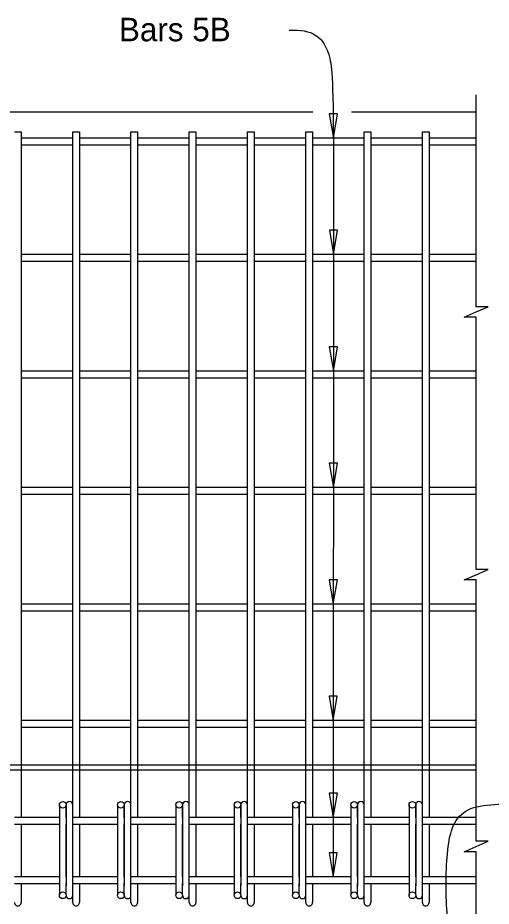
# Model space of a CAD drawing. Extents: x 120577.8 to 120649.9, y 120677.2 to 120721.6.
# Drawn here: x 120588.7 to 120592.76, y 120707.21 to 120714.84 of the extents above; entities that cross this region are included whole.
import ezdxf

# ---------------------------------------------------------------- set-up
doc = ezdxf.new("R2010")
doc.units = 0
for name, color, linetype in [('AdhocPoint_dp', 7, 'Continuous'), ('Patterning', 7, 'Continuous'), ('PlotBorder_dp', 7, 'Continuous'), ('TextMisc', 7, 'Continuous')]:
    doc.layers.add(name, color=color, linetype=linetype)

msp = doc.modelspace()

# ---------------------------------------------------------------- linework, layer by layer
at = {"layer": 'Patterning'}
for p, q in [((120588.669, 120713.8614), (120588.7263, 120713.8614)), ((120588.7263, 120713.8614), (120588.7263, 120707.9744)), ((120589.169, 120707.2437), (120589.169, 120713.8614)), ((120589.169, 120713.8614), (120589.2263, 120713.8614)), ((120589.2263, 120713.8614), (120589.2263, 120707.9744)), ((120589.669, 120707.2437), (120589.669, 120713.8614)), ((120589.669, 120713.8614), (120589.7263, 120713.8614)), ((120589.7263, 120713.8614), (120589.7263, 120707.9744)), ((120590.169, 120707.2437), (120590.169, 120713.8614)), ((120590.169, 120713.8614), (120590.2263, 120713.8614)), ((120590.2263, 120713.8614), (120590.2263, 120707.9744)), ((120590.669, 120707.2437), (120590.669, 120713.8614)), ((120590.669, 120713.8614), (120590.7263, 120713.8614)), ((120590.7263, 120713.8614), (120590.7263, 120707.9744)), ((120591.169, 120707.2437), (120591.169, 120713.8614)), ((120591.169, 120713.8614), (120591.2263, 120713.8614)), ((120591.2263, 120713.8614), (120591.2263, 120707.9744)), ((120591.669, 120707.2437), (120591.669, 120713.8614)), ((120591.669, 120713.8614), (120591.7263, 120713.8614)), ((120591.7263, 120713.8614), (120591.7263, 120707.9744)), ((120592.169, 120707.2437), (120592.169, 120713.8614)), ((120592.169, 120713.8614), (120592.2263, 120713.8614)), ((120592.2263, 120713.8614), (120592.2263, 120707.9744)), ((120589.0544, 120708.0827), (120589.0544, 120707.3067)), ((120589.1117, 120707.9744), (120589.1117, 120708.0827)), ((120589.1117, 120708.0827), (120589.1117, 120707.3872)), ((120589.5544, 120708.0827), (120589.5544, 120707.3067)), ((120589.6117, 120707.9744), (120589.6117, 120708.0827)), ((120589.6117, 120708.0827), (120589.6117, 120707.3872)), ((120590.0544, 120708.0827), (120590.0544, 120707.3067)), ((120590.1117, 120707.9744), (120590.1117, 120708.0827)), ((120590.1117, 120708.0827), (120590.1117, 120707.3872)), ((120590.5544, 120708.0827), (120590.5544, 120707.3067)), ((120590.6117, 120707.9744), (120590.6117, 120708.0827)), ((120590.6117, 120708.0827), (120590.6117, 120707.3872)), ((120591.0544, 120708.0827), (120591.0544, 120707.3067)), ((120591.1117, 120707.9744), (120591.1117, 120708.0827)), ((120591.1117, 120708.0827), (120591.1117, 120707.3872)), ((120591.5544, 120708.0827), (120591.5544, 120707.3067)), ((120591.6117, 120707.9744), (120591.6117, 120708.0827)), ((120591.6117, 120708.0827), (120591.6117, 120707.3872)), ((120592.0544, 120708.0827), (120592.0544, 120707.3067)), ((120592.1117, 120707.9744), (120592.1117, 120708.0827)), ((120592.1117, 120708.0827), (120592.1117, 120707.3872)), ((120588.7263, 120707.9172), (120588.7263, 120707.4641)), ((120589.1117, 120707.4641), (120589.1117, 120707.9172)), ((120589.2263, 120707.9172), (120589.2263, 120707.4641)), ((120589.6117, 120707.4641), (120589.6117, 120707.9172)), ((120589.7263, 120707.9172), (120589.7263, 120707.4641)), ((120590.1117, 120707.4641), (120590.1117, 120707.9172)), ((120590.2263, 120707.9172), (120590.2263, 120707.4641)), ((120590.6117, 120707.4641), (120590.6117, 120707.9172)), ((120590.7263, 120707.9172), (120590.7263, 120707.4641)), ((120591.1117, 120707.4641), (120591.1117, 120707.9172)), ((120591.2263, 120707.9172), (120591.2263, 120707.4641)), ((120591.6117, 120707.4641), (120591.6117, 120707.9172)), ((120591.7263, 120707.9172), (120591.7263, 120707.4641)), ((120592.1117, 120707.4641), (120592.1117, 120707.9172)), ((120592.2263, 120707.9172), (120592.2263, 120707.4641)), ((120588.7263, 120707.4069), (120588.7263, 120707.2437)), ((120589.1117, 120707.3067), (120589.1117, 120707.4069)), ((120589.2263, 120707.4069), (120589.2263, 120707.2437)), ((120589.6117, 120707.3067), (120589.6117, 120707.4069)), ((120589.7263, 120707.4069), (120589.7263, 120707.2437)), ((120590.1117, 120707.3067), (120590.1117, 120707.4069)), ((120590.2263, 120707.4069), (120590.2263, 120707.2437)), ((120590.6117, 120707.3067), (120590.6117, 120707.4069)), ((120590.7263, 120707.4069), (120590.7263, 120707.2437)), ((120591.1117, 120707.3067), (120591.1117, 120707.4069)), ((120591.2263, 120707.4069), (120591.2263, 120707.2437)), ((120591.6117, 120707.3067), (120591.6117, 120707.4069)), ((120591.7263, 120707.4069), (120591.7263, 120707.2437)), ((120592.1117, 120707.3067), (120592.1117, 120707.4069)), ((120592.2263, 120707.4069), (120592.2263, 120707.2437))]:
    msp.add_line(p, q, dxfattribs=at)
for points in [[(120589.169, 120713.8067), (120588.7263, 120713.8067)], [(120589.669, 120713.8067), (120589.2263, 120713.8067)], [(120590.169, 120713.8067), (120589.7263, 120713.8067)], [(120590.669, 120713.8067), (120590.2263, 120713.8067)], [(120591.169, 120713.8067), (120590.7263, 120713.8067)], [(120591.669, 120713.8067), (120591.2263, 120713.8067)], [(120592.169, 120713.8067), (120591.7263, 120713.8067)], [(120592.6308, 120713.8067), (120592.2263, 120713.8067)], [(120588.7263, 120713.7494), (120589.169, 120713.7494)], [(120589.2263, 120713.7494), (120589.669, 120713.7494)], [(120589.7263, 120713.7494), (120590.169, 120713.7494)], [(120590.2263, 120713.7494), (120590.669, 120713.7494)], [(120590.7263, 120713.7494), (120591.169, 120713.7494)], [(120591.2263, 120713.7494), (120591.669, 120713.7494)], [(120591.7263, 120713.7494), (120592.169, 120713.7494)], [(120592.2263, 120713.7494), (120592.6308, 120713.7494)], [(120589.169, 120712.8067), (120588.7263, 120712.8067)], [(120589.669, 120712.8067), (120589.2263, 120712.8067)], [(120590.169, 120712.8067), (120589.7263, 120712.8067)], [(120590.669, 120712.8067), (120590.2263, 120712.8067)], [(120591.169, 120712.8067), (120590.7263, 120712.8067)], [(120591.669, 120712.8067), (120591.2263, 120712.8067)], [(120592.169, 120712.8067), (120591.7263, 120712.8067)], [(120592.6308, 120712.8067), (120592.2263, 120712.8067)], [(120588.7263, 120712.7494), (120589.169, 120712.7494)], [(120589.2263, 120712.7494), (120589.669, 120712.7494)], [(120589.7263, 120712.7494), (120590.169, 120712.7494)], [(120590.2263, 120712.7494), (120590.669, 120712.7494)], [(120590.7263, 120712.7494), (120591.169, 120712.7494)], [(120591.2263, 120712.7494), (120591.669, 120712.7494)], [(120591.7263, 120712.7494), (120592.169, 120712.7494)], [(120592.2263, 120712.7494), (120592.6308, 120712.7494)], [(120589.169, 120711.8067), (120588.7263, 120711.8067)], [(120588.7263, 120711.7494), (120589.169, 120711.7494)], [(120589.669, 120711.8067), (120589.2263, 120711.8067)], [(120589.2263, 120711.7494), (120589.669, 120711.7494)], [(120590.169, 120711.8067), (120589.7263, 120711.8067)], [(120589.7263, 120711.7494), (120590.169, 120711.7494)], [(120590.669, 120711.8067), (120590.2263, 120711.8067)], [(120590.2263, 120711.7494), (120590.669, 120711.7494)], [(120591.169, 120711.8067), (120590.7263, 120711.8067)], [(120590.7263, 120711.7494), (120591.169, 120711.7494)], [(120591.669, 120711.8067), (120591.2263, 120711.8067)], [(120591.2263, 120711.7494), (120591.669, 120711.7494)], [(120592.169, 120711.8067), (120591.7263, 120711.8067)], [(120591.7263, 120711.7494), (120592.169, 120711.7494)], [(120592.6308, 120711.8067), (120592.2263, 120711.8067)], [(120592.2263, 120711.7494), (120592.6308, 120711.7494)], [(120589.169, 120710.8067), (120588.7263, 120710.8067)], [(120588.7263, 120710.7494), (120589.169, 120710.7494)], [(120589.669, 120710.8067), (120589.2263, 120710.8067)], [(120589.2263, 120710.7494), (120589.669, 120710.7494)], [(120590.169, 120710.8067), (120589.7263, 120710.8067)], [(120589.7263, 120710.7494), (120590.169, 120710.7494)], [(120590.669, 120710.8067), (120590.2263, 120710.8067)], [(120590.2263, 120710.7494), (120590.669, 120710.7494)], [(120591.169, 120710.8067), (120590.7263, 120710.8067)], [(120590.7263, 120710.7494), (120591.169, 120710.7494)], [(120591.669, 120710.8067), (120591.2263, 120710.8067)], [(120591.2263, 120710.7494), (120591.669, 120710.7494)], [(120592.169, 120710.8067), (120591.7263, 120710.8067)], [(120591.7263, 120710.7494), (120592.169, 120710.7494)], [(120592.6308, 120710.8067), (120592.2263, 120710.8067)], [(120592.2263, 120710.7494), (120592.6308, 120710.7494)], [(120589.169, 120709.8067), (120588.7263, 120709.8067)], [(120589.669, 120709.8067), (120589.2263, 120709.8067)], [(120590.169, 120709.8067), (120589.7263, 120709.8067)], [(120590.669, 120709.8067), (120590.2263, 120709.8067)], [(120591.169, 120709.8067), (120590.7263, 120709.8067)], [(120591.669, 120709.8067), (120591.2263, 120709.8067)], [(120592.169, 120709.8067), (120591.7263, 120709.8067)], [(120592.6308, 120709.8067), (120592.2263, 120709.8067)], [(120588.7263, 120709.7494), (120589.169, 120709.7494)], [(120589.2263, 120709.7494), (120589.669, 120709.7494)], [(120589.7263, 120709.7494), (120590.169, 120709.7494)], [(120590.2263, 120709.7494), (120590.669, 120709.7494)], [(120590.7263, 120709.7494), (120591.169, 120709.7494)], [(120591.2263, 120709.7494), (120591.669, 120709.7494)], [(120591.7263, 120709.7494), (120592.169, 120709.7494)], [(120592.2263, 120709.7494), (120592.6308, 120709.7494)], [(120589.169, 120708.8067), (120588.7263, 120708.8067)], [(120589.669, 120708.8067), (120589.2263, 120708.8067)], [(120590.169, 120708.8067), (120589.7263, 120708.8067)], [(120590.669, 120708.8067), (120590.2263, 120708.8067)], [(120591.169, 120708.8067), (120590.7263, 120708.8067)], [(120591.669, 120708.8067), (120591.2263, 120708.8067)], [(120592.169, 120708.8067), (120591.7263, 120708.8067)], [(120592.6308, 120708.8067), (120592.2263, 120708.8067)], [(120588.7263, 120708.7494), (120589.169, 120708.7494)], [(120589.2263, 120708.7494), (120589.669, 120708.7494)], [(120589.7263, 120708.7494), (120590.169, 120708.7494)], [(120590.2263, 120708.7494), (120590.669, 120708.7494)], [(120590.7263, 120708.7494), (120591.169, 120708.7494)], [(120591.2263, 120708.7494), (120591.669, 120708.7494)], [(120591.7263, 120708.7494), (120592.169, 120708.7494)], [(120592.2263, 120708.7494), (120592.6308, 120708.7494)], [(120589.0544, 120707.9744), (120588.669, 120707.9744)], [(120589.5544, 120707.9744), (120589.169, 120707.9744)], [(120590.0544, 120707.9744), (120589.669, 120707.9744)], [(120590.5544, 120707.9744), (120590.169, 120707.9744)], [(120591.0544, 120707.9744), (120590.669, 120707.9744)], [(120591.5544, 120707.9744), (120591.169, 120707.9744)], [(120592.0544, 120707.9744), (120591.669, 120707.9744)], [(120592.6308, 120707.9744), (120592.169, 120707.9744)], [(120588.669, 120707.9172), (120589.0544, 120707.9172)], [(120589.169, 120707.9172), (120589.5544, 120707.9172)], [(120589.669, 120707.9172), (120590.0544, 120707.9172)], [(120590.169, 120707.9172), (120590.5544, 120707.9172)], [(120590.669, 120707.9172), (120591.0544, 120707.9172)], [(120591.169, 120707.9172), (120591.5544, 120707.9172)], [(120591.669, 120707.9172), (120592.0544, 120707.9172)], [(120592.169, 120707.9172), (120592.6308, 120707.9172)], [(120589.0544, 120707.4641), (120588.669, 120707.4641)], [(120589.5544, 120707.4641), (120589.169, 120707.4641)], [(120590.0544, 120707.4641), (120589.669, 120707.4641)], [(120590.5544, 120707.4641), (120590.169, 120707.4641)], [(120591.0544, 120707.4641), (120590.669, 120707.4641)], [(120591.5544, 120707.4641), (120591.169, 120707.4641)], [(120592.0544, 120707.4641), (120591.669, 120707.4641)], [(120592.6308, 120707.4641), (120592.169, 120707.4641)], [(120588.669, 120707.4069), (120589.0544, 120707.4069)], [(120589.169, 120707.4069), (120589.5544, 120707.4069)], [(120589.669, 120707.4069), (120590.0544, 120707.4069)], [(120590.169, 120707.4069), (120590.5544, 120707.4069)], [(120590.669, 120707.4069), (120591.0544, 120707.4069)], [(120591.169, 120707.4069), (120591.5544, 120707.4069)], [(120591.669, 120707.4069), (120592.0544, 120707.4069)], [(120592.169, 120707.4069), (120592.6308, 120707.4069)]]:
    msp.add_lwpolyline(points, dxfattribs=at)
for centre in [(120589.0831, 120708.0827), (120589.5831, 120708.0827), (120590.0831, 120708.0827), (120590.5831, 120708.0827), (120591.0831, 120708.0827), (120591.5831, 120708.0827), (120592.0831, 120708.0827), (120589.0831, 120707.3067), (120589.5831, 120707.3067), (120590.0831, 120707.3067), (120590.5831, 120707.3067), (120591.0831, 120707.3067), (120591.5831, 120707.3067), (120592.0831, 120707.3067)]:
    msp.add_circle(centre, 0.0286, dxfattribs=at)
for centre, start, end in [((120589.1404, 120708.0827), 0, 180), ((120589.6404, 120708.0827), 0, 180), ((120590.1404, 120708.0827), 0, 180), ((120590.6404, 120708.0827), 0, 180), ((120591.1404, 120708.0827), 0, 180), ((120591.6404, 120708.0827), 0, 180), ((120592.1404, 120708.0827), 0, 180), ((120588.6977, 120707.2442), 179.02288, 0.97712), ((120589.1404, 120707.3067), 180, 0), ((120589.1977, 120707.2442), 179.02288, 0.97712), ((120589.6404, 120707.3067), 180, 0), ((120589.6977, 120707.2442), 179.02288, 0.97712), ((120590.1404, 120707.3067), 180, 0), ((120590.1977, 120707.2442), 179.02288, 0.97712), ((120590.6404, 120707.3067), 180, 0), ((120590.6977, 120707.2442), 179.02288, 0.97712), ((120591.1404, 120707.3067), 180, 0), ((120591.1977, 120707.2442), 179.02288, 0.97712), ((120591.6404, 120707.3067), 180, 0), ((120591.6977, 120707.2442), 179.02288, 0.97712), ((120592.1404, 120707.3067), 180, 0), ((120592.1977, 120707.2442), 179.02288, 0.97712)]:
    msp.add_arc(centre, 0.0286, start, end, dxfattribs=at)
at = {"layer": 'PlotBorder_dp'}
for points in [[(120592.6307, 120710.7494), (120592.6307, 120712.2689), (120592.5274, 120712.2689), (120592.6307, 120712.3139), (120592.7341, 120712.3589), (120592.6307, 120712.3589), (120592.6307, 120714.178)], [(120592.6307, 120708.4239), (120592.6307, 120710.0138), (120592.5274, 120710.0138), (120592.6307, 120710.0588), (120592.7341, 120710.1038), (120592.6307, 120710.1038), (120592.6307, 120710.7494)], [(120592.6308, 120706.878), (120592.6308, 120707.6809), (120592.5274, 120707.6809), (120592.6308, 120707.7259), (120592.7341, 120707.7709), (120592.6308, 120707.7709), (120592.6308, 120708.4238)]]:
    msp.add_lwpolyline(points, dxfattribs=at)
for points in [[(120591.4058, 120713.8067), (120591.4412, 120714.015), (120591.3707, 120714.015)], [(120591.4068, 120712.8067), (120591.4422, 120713.015), (120591.3716, 120713.015)], [(120591.4055, 120711.8067), (120591.4408, 120712.015), (120591.3703, 120712.015)], [(120591.4057, 120710.8067), (120591.4411, 120711.0149), (120591.3705, 120711.0149)], [(120591.4047, 120709.8067), (120591.4401, 120710.0149), (120591.3696, 120710.0149)], [(120591.404, 120708.8067), (120591.4393, 120709.0149), (120591.3688, 120709.0149)], [(120591.4042, 120707.9745), (120591.4395, 120708.1827), (120591.369, 120708.1827)], [(120591.4034, 120707.4642), (120591.4388, 120707.6724), (120591.3682, 120707.6724)]]:
    msp.add_lwpolyline(points, close=True, dxfattribs=at)
for points in [[(120591.0263, 120714.732), (120591.2193, 120714.7423), (120591.4373, 120714.6299), (120591.4053, 120713.9536), (120591.4034, 120707.4642)], [(120592.6472, 120706.6314), (120592.5646, 120706.651), (120592.4421, 120706.7488), (120592.3683, 120707.1195), (120592.3683, 120707.7358), (120592.4817, 120708.1066), (120593.0792, 120708.0827), (120593.5792, 120708.0827), (120594.0792, 120708.0827), (120594.5792, 120708.0827), (120595.0792, 120708.0827)]]:
    msp.add_open_spline(points, degree=3, dxfattribs=at)
at = {"layer": 'TextMisc'}
for p, q in [((120588.7893, 120714.028), (120586.866, 120714.028)), ((120591.2306, 120714.028), (120588.7893, 120714.028)), ((120592.6307, 120714.028), (120591.5604, 120714.028)), ((120592.6308, 120708.4238), (120585.3644, 120708.4238)), ((120592.6308, 120708.3822), (120585.3644, 120708.3822))]:
    msp.add_line(p, q, dxfattribs=at)

# ---------------------------------------------------------------- texts
at = {"layer": 'AdhocPoint_dp'}
msp.add_text('Bars 5B', height=0.2016, dxfattribs=at).set_placement((120589.5656, 120714.6377))

doc.saveas('drawing.dxf')
